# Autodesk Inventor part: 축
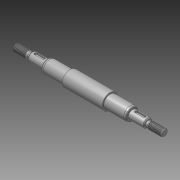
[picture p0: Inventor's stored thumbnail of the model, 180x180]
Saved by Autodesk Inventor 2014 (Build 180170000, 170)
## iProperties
Created: 2015-11
Part Number: 축
Material: 강철, 연강
Document SubType Name: Modeling
Designer: mduedu
Density: 7.86 g/cm^3
Mass: 198.507 g
Surface Area: 75.8873 cm^2
Volume: 25.2553 cm^3
Appearance: 강철
Author: mduedu
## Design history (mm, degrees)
sketch "스케치1"
  geometry: L1 (-86, 0)-(86, 0); L2 (-86, 0)-(-86, 4); L3 (-86, 4)-(-70.732, 4); L4 (-70.732, 4)-(-69, 3); L5 (-69, 3)-(-67, 3); L6 (-67, 3)-(-67, 5); L7 (-67, 5)-(-49, 5); L8 (-49, 5)-(-49, 6.55); L9 (-47.355, 7.5)-(-23, 7.5); L10 (-23, 7.5)-(-23, 9); L11 (0, 0)-(0, 9); L12 (86, 4)-(70.732, 4); L13 (70.732, 4)-(69, 3); L14 (69, 3)-(67, 3); L15 (67, 3)-(67, 5); L16 (67, 5)-(49, 5); L17 (23, 7.5)-(23, 9); L18 (86, 0)-(86, 4); L19 (-23, 9)-(23, 9); L20 (-49, 6.55)-(-47.355, 7.5); L21 (47.355, 7.5)-(23, 7.5); L22 (49, 6.55)-(47.355, 7.5); L23 (49, 5)-(49, 6.55); 1 further point
  constraints: 46 end point, 10 symmetric about line, 6 perpendicular, 5 parallel, 2 midpoint, 1 coincident, 1 horizontal
  dimensions: "d0" = 172 distance of L1.start L1.end (derived); "d1" = 8 diameter of L3 L1; "d2" = 30 deg angle of L4 L5; "d3" = 6 diameter of L5 L1; "d4" = 10 diameter of L7 L1; "d5" = 15 diameter of L9 L1; "d6" = 18 diameter of L19 L1; "d8" = 18 distance of L6.end L7.end; "d9" = 46 distance of L10.end L17.end; "d10" = 2 distance of L4.end L5.end; "d11" = 17 distance from line of L4.end L2; "d16" = 13.1 diameter of L8.end L1; "d17" = 30 deg angle of L20 L9; "d18" = 26 distance between parallel lines of L10 L8
revolve "회전1" sketch "스케치1" stored, may be unused: angle "d12" = 90 deg
chamfer "모따기1" distance "d13" = 1; stored, may be unused: second distance "d14" = 2, angle "d15" = 45 deg
fillet "모깎기1" dims "d19" = 4, "d20" = 0.5
node "작업 평면1"
sketch "스케치2" dims "d23" = 12
  geometry: L1 (-4.5, 1.5)-(4.5, 1.5); L2 (4.5, 1.5)-(4.5, -1.5); L3 (4.5, -1.5)-(-4.5, -1.5); L4 (-4.5, -1.5)-(-4.5, 1.5); L5 (-9, -4)-(-9, 4) reference; 3 further points
  constraints: 8 end point, 2 midpoint, 2 parallel, 2 vertical alignment, 1 horizontal, 1 perpendicular, 4 other
  dimensions: "d21" = 3 distance between parallel lines of L3 L1; "d24" = 3 dimension on L5
extrude "돌출1" cut sketch "스케치2" distance "d25" = 1.8; taper "d26" = 0 deg
feature "스레드1" dims "d27" = 10, "d28" = 0
feature "스레드2" dims "d29" = 10, "d30" = 0
chamfer "모따기2" distance "d31" = 1; stored, may be unused: second distance "d32" = 2, angle "d33" = 45 deg
fillet "모깎기2" dims "d34" = 0.3
node "솔리드1"
mirror "대칭1"
